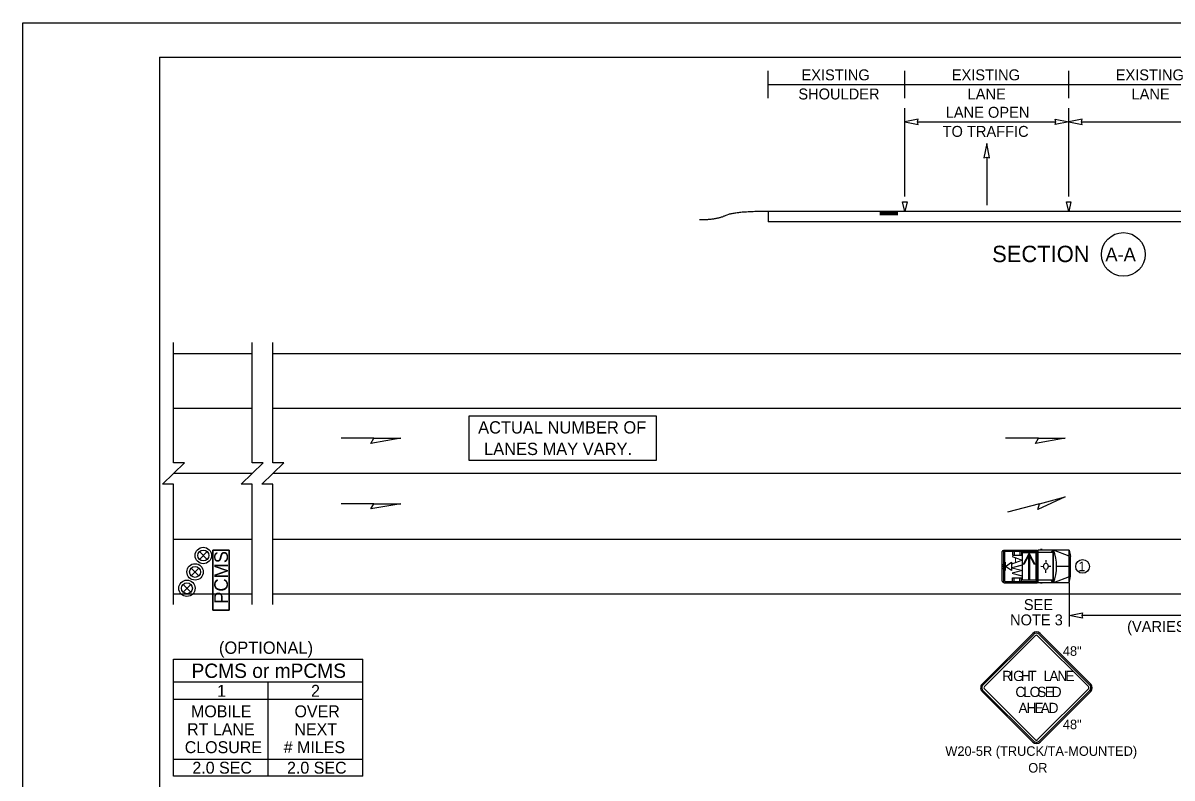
# Model space of a CAD drawing. Extents: x 0 to 17, y 0 to 11.
# Drawn here: x 0 to 8.41, y 5.47 to 11 of the extents above; entities that cross this region are included whole.
import ezdxf

# ---------------------------------------------------------------- set-up
doc = ezdxf.new("R2010")
doc.units = 0
for name, color, linetype in [('RD_ED_ShoulderPavedEdge', 7, 'Continuous'), ('RD_MK_LineEdgeWhite', 7, 'Continuous'), ('RD_MK_LineEdgeYellow', 7, 'Continuous'), ('RD_MK_LineLane', 7, 'Continuous'), ('SH_GI_PlotLimits', 7, 'Continuous'), ('SH_GI_SheetBorder3', 7, 'Continuous'), ('SH_TI_Tables', 7, 'Continuous'), ('SH_TI_WZSectionCut', 7, 'Continuous'), ('TR_SN_ConstructionSigns', 7, 'Continuous'), ('TR_WZ_ArrowLeftStrRightTurn', 7, 'Continuous'), ('TR_WZ_PCMS', 7, 'Continuous'), ('TR_WZ_PortableChangeMessageSign', 7, 'Continuous'), ('TR_WZ_PortableSignMountBlk-Org', 7, 'Continuous'), ('TR_WZ_ProtectiveVehicle', 7, 'Continuous'), ('TR_WZ_TrafficSafetyDrum', 7, 'Continuous'), ('TR_WZ_TransportableAttenuator', 7, 'Continuous'), ('TR_WZ_WorkZoneDetails', 7, 'Continuous'), ('TR_WZ_WorkZoneTextCurrent', 7, 'Continuous')]:
    doc.layers.add(name, color=color, linetype=linetype)

msp = doc.modelspace()

# ---------------------------------------------------------------- linework, layer by layer
at = {"layer": 'RD_ED_ShoulderPavedEdge'}
for p, q in [((1.1016, 8.5807), (1.6783, 8.5807)), ((1.8283, 8.5807), (16.62, 8.5807)), ((1.1016, 6.8207), (1.6783, 6.8207)), ((1.8283, 6.8207), (16.62, 6.8207))]:
    msp.add_line(p, q, dxfattribs=at)
at = {"layer": 'RD_MK_LineEdgeWhite'}
for p, q in [((1.1016, 7.2207), (1.6783, 7.2207)), ((1.8283, 7.2207), (16.62, 7.2207))]:
    msp.add_line(p, q, dxfattribs=at)
at = {"layer": 'RD_MK_LineEdgeYellow'}
for p, q in [((1.1016, 8.1807), (1.6783, 8.1807)), ((1.8283, 8.1807), (16.62, 8.1807))]:
    msp.add_line(p, q, dxfattribs=at)
at = {"layer": 'RD_MK_LineLane'}
for p, q in [((1.6783, 7.7007), (1.1016, 7.7007)), ((16.62, 7.7007), (1.8283, 7.7007))]:
    msp.add_line(p, q, dxfattribs=at)
at = {"layer": 'SH_GI_PlotLimits'}
msp.add_lwpolyline([(0, 11), (17, 11), (17, 0), (0, 0)], close=True, dxfattribs=at)
at = {"layer": 'SH_GI_SheetBorder3'}
for q in [(16.75, 10.75), (1, 0.25)]:
    msp.add_line((1, 10.75), q, dxfattribs=at)
at = {"layer": 'SH_TI_Tables'}
msp.add_lwpolyline([(3.266, 8.1232), (4.6358, 8.1232), (4.6358, 7.7968), (3.266, 7.7968)], close=True, dxfattribs=at)
at = {"layer": 'SH_TI_WZSectionCut'}
for p, q in [((5.4546, 10.45), (5.4546, 10.65)), ((6.4546, 10.45), (6.4546, 10.65)), ((7.6546, 10.45), (7.6546, 10.65)), ((5.4546, 10.55), (6.4546, 10.55)), ((6.4546, 10.55), (7.6546, 10.55)), ((7.6546, 10.55), (8.8546, 10.55)), ((6.4546, 9.7297), (6.4546, 10.376)), ((7.6546, 9.7297), (7.6546, 10.376)), ((6.5484, 10.276), (7.5609, 10.276)), ((7.7484, 10.276), (9.7609, 10.276)), ((5.4546, 9.6199), (5.4546, 9.5449)), ((9.8546, 9.6199), (5.4546, 9.6199)), ((6.2716, 9.6147), (6.4046, 9.6147)), ((6.2716, 9.6091), (6.4046, 9.6091)), ((6.2716, 9.6034), (6.4046, 9.6034)), ((6.2716, 9.5982), (6.4046, 9.5982)), ((9.8546, 9.5449), (5.4546, 9.5449))]:
    msp.add_line(p, q, dxfattribs=at)
for points in [[(6.4546, 10.276), (6.5529, 10.2567), (6.5484, 10.276), (6.5529, 10.2953)], [(7.6546, 10.276), (7.5564, 10.2567), (7.5609, 10.276), (7.5564, 10.2953)], [(7.6546, 10.276), (7.7529, 10.2567), (7.7484, 10.276), (7.7529, 10.2953)], [(6.4379, 9.6897), (6.4713, 9.6897), (6.4546, 9.6199)], [(7.638, 9.6897), (7.6713, 9.6897), (7.6547, 9.6199)]]:
    msp.add_lwpolyline(points, close=True, dxfattribs=at)
msp.add_circle((8.055, 9.305), 0.16, dxfattribs=at)
msp.add_open_spline([(5.4546, 9.6199), (5.2035, 9.6199), (5.078, 9.5578), (4.9525, 9.5578)], degree=2, dxfattribs=at)
at = {"layer": 'TR_SN_ConstructionSigns'}
for p, q in [((7.3917, 6.5301), (7.0205, 6.1588)), ((7.3984, 6.5234), (7.0271, 6.1522)), ((7.0382, 6.1411), (7.4094, 6.5124)), ((7.4271, 6.5124), (7.7983, 6.1411)), ((7.8094, 6.1522), (7.4381, 6.5234)), ((7.816, 6.1588), (7.4448, 6.5301)), ((7.0205, 6.1058), (7.3917, 5.7345)), ((7.0271, 6.1124), (7.3984, 5.7412)), ((7.4094, 5.7522), (7.0382, 6.1235)), ((7.7983, 6.1235), (7.4271, 5.7522)), ((7.4381, 5.7412), (7.8094, 6.1124)), ((7.4448, 5.7345), (7.816, 6.1058))]:
    msp.add_line(p, q, dxfattribs=at)
for centre, radius, start, end in [((7.4183, 6.5036), 0.0375, 45, 135), ((7.4183, 6.5036), 0.0281, 45, 135), ((7.4183, 6.5036), 0.0125, 45, 135), ((7.047, 6.1323), 0.0375, 135, 225.00001), ((7.047, 6.1323), 0.0281, 135, 225.00001), ((7.047, 6.1323), 0.0125, 135, 225.00001), ((7.7895, 6.1323), 0.0125, 315.00002, 45), ((7.7895, 6.1323), 0.0281, 315.00002, 45), ((7.7895, 6.1323), 0.0375, 315.00001, 45.00001), ((7.4183, 5.7611), 0.0375, 225.00001, 315.00001), ((7.4183, 5.7611), 0.0281, 225.00001, 315.00002), ((7.4183, 5.7611), 0.0125, 225.00001, 315.00002)]:
    msp.add_arc(centre, radius, start, end, dxfattribs=at)
at = {"layer": 'TR_WZ_ArrowLeftStrRightTurn'}
msp.add_line((7.0546, 10.0168), (7.0546, 9.667), dxfattribs=at)
msp.add_lwpolyline([(7.0546, 10.117), (7.034, 10.0119), (7.0546, 10.0168), (7.0752, 10.0119)], close=True, dxfattribs=at)
at = {"layer": 'TR_WZ_PCMS'}
for points in [[(1.39, 7.1407), (1.51, 7.1407), (1.51, 6.7007), (1.39, 6.7007), (1.39, 7.1407)], [(1.39, 6.7007), (1.51, 6.7007), (1.51, 7.1407), (1.39, 7.1407), (1.39, 6.7007)]]:
    msp.add_lwpolyline(points, dxfattribs=at)
at = {"layer": 'TR_WZ_PortableChangeMessageSign'}
for p, q in [((1.1016, 6.3407), (2.4876, 6.3407)), ((1.1016, 5.4839), (1.1016, 6.3407)), ((2.4876, 5.4839), (2.4876, 6.3407)), ((2.4876, 6.1727), (1.1016, 6.1727)), ((1.7946, 5.4839), (1.7946, 6.1727)), ((1.7946, 6.0467), (1.1016, 6.0467)), ((2.4876, 6.0467), (1.7946, 6.0467)), ((1.1016, 5.6099), (1.7946, 5.6099)), ((1.7946, 5.6099), (2.4876, 5.6099)), ((2.4876, 5.4839), (1.1016, 5.4839))]:
    msp.add_line(p, q, dxfattribs=at)
at = {"layer": 'TR_WZ_PortableSignMountBlk-Org'}
msp.add_line((7.1919, 6.9907), (7.1919, 7.0507), dxfattribs=at)
msp.add_lwpolyline([(7.1919, 7.0207), (7.235, 7.0507), (7.235, 6.9907)], close=True, dxfattribs=at)
at = {"layer": 'TR_WZ_ProtectiveVehicle'}
for p, q in [((7.1685, 6.912), (7.1685, 7.1295)), ((7.1739, 7.1368), (7.1792, 7.1368)), ((7.1792, 6.9047), (7.1792, 7.1368)), ((7.18, 7.1407), (7.4269, 7.1407)), ((7.18, 6.9007), (7.18, 7.1407)), ((7.187, 6.9103), (7.187, 7.1312)), ((7.187, 7.1312), (7.4199, 7.1312)), ((7.2427, 7.1312), (7.2427, 7.1035)), ((7.2427, 7.1035), (7.3086, 7.1035)), ((7.2559, 7.1312), (7.2559, 7.1035)), ((7.2967, 7.1312), (7.2967, 7.1035)), ((7.3086, 7.1312), (7.3086, 7.1035)), ((7.4199, 6.9103), (7.4199, 7.1312)), ((7.4269, 6.9007), (7.4269, 7.1407)), ((7.4302, 6.9007), (7.4302, 7.1407)), ((7.6569, 7.1407), (7.4302, 7.1407)), ((7.5415, 7.1221), (7.4302, 7.1221)), ((7.4611, 7.1441), (7.4475, 7.1441)), ((7.4862, 7.0669), (7.4866, 7.0488)), ((7.5295, 7.1221), (7.5415, 7.1407)), ((7.5415, 6.9007), (7.5415, 7.1407)), ((7.5435, 6.9007), (7.5435, 7.1407)), ((7.6569, 7.0968), (7.5435, 7.1407)), ((7.6569, 6.9007), (7.6569, 7.1407)), ((7.6569, 7.1407), (7.668, 7.0923)), ((7.668, 6.9492), (7.668, 7.0923)), ((7.1685, 7.0376), (7.1792, 7.0331)), ((7.1685, 7.0038), (7.1792, 7.0083)), ((7.1714, 7.0207), (7.1763, 7.0207)), ((7.1739, 7.0173), (7.1739, 7.0241)), ((7.4501, 7.0216), (7.4679, 7.0212)), ((7.4702, 7.0211), (7.4702, 7.0211)), ((7.4871, 6.9732), (7.4871, 6.9925)), ((7.5233, 7.0206), (7.5081, 7.0206)), ((7.6569, 7.0207), (7.5658, 7.0207)), ((7.1739, 6.9047), (7.1792, 6.9047)), ((7.18, 6.9007), (7.4269, 6.9007)), ((7.187, 6.9103), (7.4199, 6.9103)), ((7.2427, 6.9379), (7.3086, 6.9379)), ((7.2427, 6.9103), (7.2427, 6.9379)), ((7.2559, 6.9103), (7.2559, 6.9379)), ((7.2967, 6.9103), (7.2967, 6.9379)), ((7.3086, 6.9103), (7.3086, 6.9379)), ((7.5415, 6.9193), (7.4302, 6.9193)), ((7.6569, 6.9007), (7.4302, 6.9007)), ((7.4611, 6.8973), (7.4475, 6.8973)), ((7.5415, 6.9007), (7.5271, 6.9193)), ((7.6569, 6.9447), (7.5435, 6.9007)), ((7.6569, 6.9007), (7.668, 6.9492))]:
    msp.add_line(p, q, dxfattribs=at)
for centre, major_axis, start_param, end_param in [((7.1739, 7.1295), (0, 0.00732), 0, 1.570796), ((7.3816, 7.0208), (0, 0.2518), 4.215667, 5.208926), ((7.1739, 6.912), (0, -0.00732), 4.712389, 6.283185)]:
    msp.add_ellipse(centre, major_axis=major_axis, ratio=0.73155, start_param=start_param, end_param=end_param, dxfattribs=at)
for centre, major_axis in [((7.1739, 7.0207), (0, -0.00338)), ((7.4871, 7.0207), (0, -0.0231))]:
    msp.add_ellipse(centre, major_axis=major_axis, ratio=0.73155, dxfattribs=at)
at = {"layer": 'TR_WZ_TrafficSafetyDrum'}
for p, q in [((1.2917, 7.129), (1.3483, 7.0724)), ((1.3483, 7.129), (1.2917, 7.0724)), ((1.2317, 7.009), (1.2883, 6.9524)), ((1.2883, 7.009), (1.2317, 6.9524)), ((1.1717, 6.889), (1.2283, 6.8324)), ((1.2283, 6.889), (1.1717, 6.8324))]:
    msp.add_line(p, q, dxfattribs=at)
for centre, radius in [((1.32, 7.1007), 0.06), ((1.32, 7.1007), 0.06), ((1.32, 7.1007), 0.04), ((1.26, 6.9807), 0.06), ((1.26, 6.9807), 0.06), ((1.26, 6.9807), 0.04), ((1.2, 6.8607), 0.06), ((1.2, 6.8607), 0.06), ((1.2, 6.8607), 0.04)]:
    msp.add_circle(centre, radius, dxfattribs=at)
at = {"layer": 'TR_WZ_TransportableAttenuator'}
for points in [[(7.3173, 7.1225), (7.4133, 7.1225), (7.4133, 6.9189), (7.3173, 6.9189)], [(7.3239, 7.0368), (7.3653, 7.1143), (7.3637, 7.1041), (7.3266, 7.0346)], [(7.3653, 7.1143), (7.3669, 7.1041), (7.3637, 7.1041)], [(7.3637, 6.9271), (7.3637, 7.1041), (7.3669, 7.1041), (7.3669, 6.9271)], [(7.3653, 7.1143), (7.4066, 7.0368), (7.4039, 7.0346), (7.3669, 7.1041)]]:
    msp.add_lwpolyline(points, close=True, dxfattribs=at)
at = {"layer": 'TR_WZ_WorkZoneDetails'}
for p, q in [((2.5694, 7.96), (2.3283, 7.96)), ((7.4331, 7.96), (7.192, 7.96)), ((2.5694, 7.48), (2.3283, 7.48)), ((7.4398, 7.48), (7.2069, 7.4176)), ((7.6569, 6.9007), (7.6569, 6.5811)), ((9.5632, 6.6611), (7.7506, 6.6611))]:
    msp.add_line(p, q, dxfattribs=at)
for points in [[(1.1016, 6.7407), (1.1016, 7.6233), (1.0216, 7.6233), (1.1817, 7.7782), (1.1016, 7.7782), (1.1016, 8.6607)], [(1.6783, 6.7407), (1.6783, 7.6233), (1.5983, 7.6233), (1.7583, 7.7782), (1.6783, 7.7782), (1.6783, 8.6607)], [(1.8283, 6.7407), (1.8283, 7.6233), (1.7483, 7.6233), (1.9083, 7.7782), (1.8283, 7.7782), (1.8283, 8.6607)]]:
    msp.add_lwpolyline(points, dxfattribs=at)
for points in [[(2.766, 7.96), (2.5471, 7.9214), (2.5694, 7.96)], [(7.6296, 7.96), (7.4108, 7.9214), (7.4331, 7.96)], [(7.6296, 7.5309), (7.4282, 7.437), (7.4398, 7.48)], [(2.766, 7.48), (2.5471, 7.4414), (2.5694, 7.48)], [(7.6569, 6.6611), (7.7552, 6.6803), (7.7506, 6.6611), (7.7552, 6.6418)]]:
    msp.add_lwpolyline(points, close=True, dxfattribs=at)
msp.add_circle((7.7561, 7.0207), 0.05, dxfattribs=at)

# ---------------------------------------------------------------- texts
at = {"layer": 'SH_TI_Tables'}
for s, p in [('ACTUAL NUMBER OF', (3.3317, 7.9938)), ('LANES MAY VARY.', (3.375, 7.8363))]:
    msp.add_text(s, height=0.09, rotation=360, dxfattribs=at).set_placement(p)
at = {"layer": 'SH_TI_WZSectionCut'}
for s, height, p in [('EXISTING', 0.08, (5.6986, 10.58)), ('EXISTING', 0.08, (6.7986, 10.58)), ('EXISTING', 0.08, (7.9986, 10.58)), ('SHOULDER', 0.08, (5.6757, 10.44)), ('LANE', 0.08, (6.9145, 10.44)), ('LANE', 0.08, (8.1145, 10.44)), ('SECTION', 0.12, (7.0943, 9.2489)), ('A-A', 0.1, (7.9231, 9.255))]:
    msp.add_text(s, height=height, rotation=360, dxfattribs=at).set_placement(p)
for s, p in [('LANE OPEN', (6.7543, 10.306)), ('TO TRAFFIC', (6.7315, 10.166))]:
    msp.add_text(s, height=0.08, dxfattribs=at).set_placement(p)
at = {"layer": 'TR_SN_ConstructionSigns'}
for s, height, p in [('48"', 0.07, (7.6119, 6.366)), ('R', 0.075, (7.1677, 6.1815)), ('I', 0.075, (7.2225, 6.1815)), ('G', 0.075, (7.248, 6.1815)), ('H', 0.075, (7.305, 6.1815)), ('T', 0.075, (7.3575, 6.1815)), ('L', 0.075, (7.4708, 6.1815)), ('A', 0.075, (7.5135, 6.1815)), ('N', 0.075, (7.572, 6.1815)), ('E', 0.075, (7.6305, 6.1815)), ('C', 0.075, (7.2645, 6.0643)), ('O', 0.075, (7.3688, 6.0643)), ('S', 0.075, (7.4243, 6.0643)), ('L', 0.075, (7.3215, 6.0643)), ('E', 0.075, (7.479, 6.0643)), ('D', 0.075, (7.53, 6.0643)), ('A', 0.075, (7.287, 5.9471)), ('H', 0.075, (7.3455, 5.9471)), ('E', 0.075, (7.404, 5.9471)), ('A', 0.075, (7.449, 5.9471)), ('D', 0.075, (7.5075, 5.9471)), ('48"', 0.07, (7.6119, 5.8286)), ('W20-5R (TRUCK/TA-MOUNTED)', 0.07, (6.7513, 5.6336)), ('OR', 0.07, (7.3584, 5.5111))]:
    msp.add_text(s, height=height, dxfattribs=at).set_placement(p)
at = {"layer": 'TR_WZ_PCMS'}
msp.add_text('PCMS', height=0.1, rotation=90, dxfattribs=at).set_placement((1.5, 6.7471))
at = {"layer": 'TR_WZ_PortableChangeMessageSign'}
for s, height, p in [('PCMS or mPCMS', 0.105, (1.2335, 6.2042)), ('1', 0.0875, (1.4208, 6.066)), ('2', 0.0875, (2.1087, 6.066)), ('MOBILE', 0.0875, (1.2299, 5.9158)), ('OVER', 0.0875, (1.9874, 5.9158)), ('RT LANE', 0.0875, (1.2015, 5.7846)), ('NEXT', 0.0875, (1.9866, 5.7846)), ('CLOSURE', 0.0875, (1.184, 5.6533)), ('# MILES', 0.0875, (1.9088, 5.6533)), ('2.0 SEC', 0.0875, (1.2399, 5.5032)), ('2.0 SEC', 0.0875, (1.9329, 5.5032))]:
    msp.add_text(s, height=height, rotation=360, dxfattribs=at).set_placement(p)
at = {"layer": 'TR_WZ_ProtectiveVehicle'}
msp.add_text('AW', height=0.07, rotation=270, dxfattribs=at).set_placement((7.2407, 7.0974))
at = {"layer": 'TR_WZ_WorkZoneDetails'}
for s, height, p in [('1', 0.07, (7.725, 6.9857)), ('(OPTIONAL)', 0.09, (1.4346, 6.3807))]:
    msp.add_text(s, height=height, dxfattribs=at).set_placement(p)
at = {"layer": 'TR_WZ_WorkZoneTextCurrent'}
for s, p in [('SEE', (7.3262, 6.7011)), ('NOTE 3', (7.2252, 6.5891)), ('(VARIES, SEE NOTE 4)', (8.0822, 6.5411))]:
    msp.add_text(s, height=0.08, dxfattribs=at).set_placement(p)

doc.saveas('drawing.dxf')
